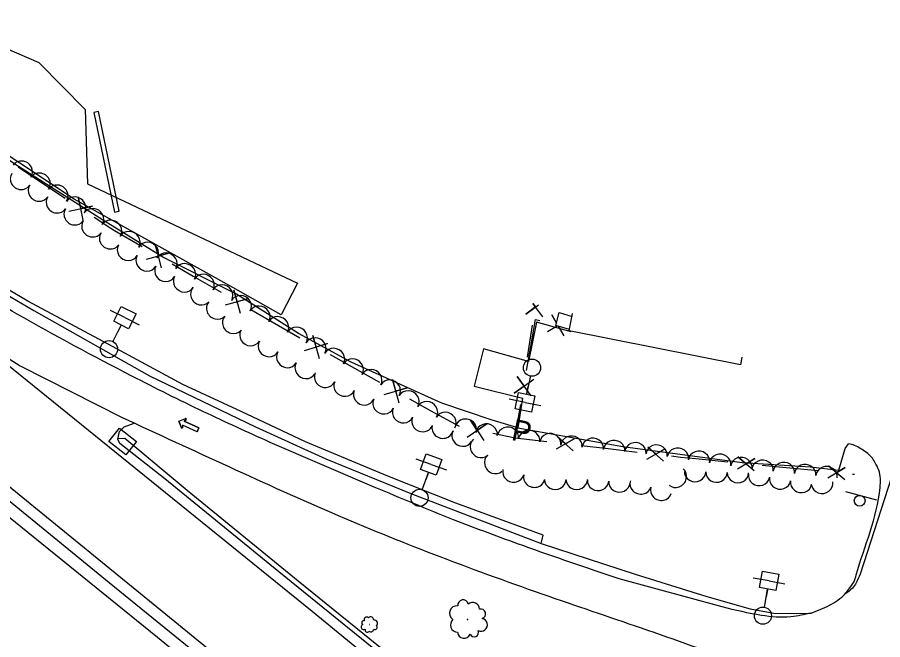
# Model space of a CAD drawing. Extents: x 1746010 to 1754829, y 655801 to 663091.
# Drawn here: x 1748666.3 to 1749070.2, y 661359.7 to 661650.3 of the extents above; entities that cross this region are included whole.
import ezdxf

# ---------------------------------------------------------------- set-up
doc = ezdxf.new("R2010")
doc.units = 0
for name, color, linetype in [('SURVEY - AERIAL SURVEY - Photo Control - Points - Elevations', 7, 'Continuous'), ('SURVEY - AERIAL SURVEY - Photo Control - Points - Locators', 7, 'Continuous'), ('SURVEY - AERIAL SURVEY - Photo Control - Points - Numbers', 7, 'Continuous'), ('SURVEY - AERIAL SURVEY - Photo Control with Text', 7, 'Continuous'), ('SURVEY - CENTERLINE - Existing Roads - Development', 7, 'Continuous'), ('SURVEY - CENTERLINE - Existing Roads Curve Text', 7, 'Continuous'), ('SURVEY - CENTERLINE - Existing Roads Text', 7, 'Continuous'), ('SURVEY - CENTERLINE - Preliminary - Development', 7, 'Continuous'), ('SURVEY - DRAINAGE - Area Shapes - Points - Elevations', 7, 'Continuous')]:
    doc.layers.add(name, color=color, linetype=linetype)

msp = doc.modelspace()

# ---------------------------------------------------------------- linework, layer by layer
at = {"layer": 'SURVEY - AERIAL SURVEY - Photo Control - Points - Elevations'}
for points in [[(1748910.83, 661404.62), (1748911.82, 661408.5), (1748870.98, 661423.43), (1748839.2, 661435.99), (1748800.89, 661452.08), (1748770.77, 661466.26), (1748743.52, 661478.84), (1748708.78, 661497.63), (1748671.19, 661517.75), (1748645.7, 661532.7), (1748625.37, 661545.71), (1748613.39, 661554.16), (1748594.67, 661567.82), (1748564.2, 661592.32), (1748517.09, 661629.66), (1748455.21, 661679.34), (1748447.39, 661684.85), (1748446.67, 661685.36)], [(1748713.37, 661453.65), (1748716.55, 661453.81), (1748746.53, 661428.67), (1748797.36, 661387.23), (1748840.72, 661352.13), (1748888.64, 661312.91), (1748914.18, 661293.34), (1748937.25, 661278.19), (1748959.67, 661261.1), (1748965.83, 661253.19), (1748993.44, 661229.06), (1749007.32, 661220.73), (1749023.86, 661206.7), (1749027.85, 661203.6), (1749026.76, 661197.6)]]:
    msp.add_lwpolyline(points, dxfattribs=at)
at = {"layer": 'SURVEY - AERIAL SURVEY - Photo Control - Points - Locators'}
for points in [[(1749014.37, 661130.26), (1748990.7, 661149.54), (1748916.31, 661209.97), (1748835.38, 661275.76), (1748731.71, 661360.72), (1748655.6, 661422.38), (1748555.07, 661504.4), (1748459.33, 661582.61), (1748380.29, 661646.59), (1748288.83, 661717.68), (1748181.12, 661800.02), (1748091.36, 661866.45), (1748036.84, 661905.72)], [(1748899.97, 661458.62), (1748887.43, 661462.28), (1748864.43, 661470.09), (1748846.92, 661477.99), (1748822.16, 661489.19), (1748797.58, 661502.72), (1748768.69, 661520.99), (1748734.27, 661538.32), (1748706.56, 661555.34), (1748665.21, 661581.73), (1748634.89, 661602.18), (1748596.11, 661629.48), (1748559.57, 661653.3), (1748537.78, 661666.72), (1748549.66, 661708.07), (1748583.03, 661703.96)], [(1748446.67, 661685.36), (1748447.41, 661681.83), (1748532.04, 661614.13), (1748593, 661565.86), (1748611.4, 661551.33), (1748626.29, 661541.43), (1748674.09, 661513.32), (1748727.97, 661482.88), (1748777.52, 661459.1), (1748810.35, 661444.15), (1748850.05, 661428.01), (1748910.83, 661404.62), (1748954.66, 661390.35), (1748988.16, 661379.8), (1749008.42, 661374.05)], [(1748523.79, 661544.26), (1748587.7, 661492.34), (1748672.29, 661423.24), (1748765.2, 661347.55), (1748850.45, 661278.14), (1748948.94, 661197.9), (1749016.8, 661142.7)], [(1748925.03, 661503.68), (1748924.84, 661503.41), (1748908.58, 661507.98), (1748904.89, 661489.51), (1748883.87, 661495.5), (1748879.53, 661478.04), (1748902.09, 661472.51), (1748899.97, 661458.62), (1748948.9, 661449.95), (1749004.58, 661442.45), (1749036.55, 661440.38), (1749049.7, 661438.78), (1749052.68, 661449.01), (1749054.28, 661451.18)], [(1749026.26, 661191.27), (1748981.31, 661227.83), (1748904.63, 661290.22), (1748803.87, 661372.8), (1748715.15, 661444.7), (1748642.21, 661503.71), (1748667.72, 661487.53), (1748715.24, 661463.43)], [(1749085.73, 661470.71), (1749059.7, 661390.3)], [(1749027.39, 661197.07), (1749014.65, 661207.7), (1748958.39, 661253.89), (1748897.1, 661302.67), (1748838.46, 661350.81), (1748788.42, 661391.33), (1748735.2, 661434.76), (1748714.24, 661451.33), (1748713.32, 661453.39), (1748714.02, 661456.96), (1748716.26, 661459.11), (1748720.91, 661460.82)], [(1748832.92, 661430.93), (1748784.36, 661451.78)], [(1748995.35, 661374.97), (1748947.23, 661388.08)], [(1749008.42, 661374.05), (1749019.46, 661372.08), (1749026.98, 661371.91), (1749036.87, 661372.11), (1749043.28, 661374.64)]]:
    msp.add_lwpolyline(points, dxfattribs=at)
for points in [[(1748784.36, 661451.78), (1748753.18, 661466.15), (1748719.83, 661482.77), (1748666.33, 661511.73), (1748631.65, 661532.7), (1748602.01, 661552.91), (1748569.65, 661577.83)], [(1748715.24, 661463.43), (1748765.05, 661440.48), (1748816.14, 661417.66), (1748863.57, 661398.48), (1748914.39, 661379.98), (1748960.41, 661364.19), (1749007.79, 661347.35)], [(1749043.28, 661374.64), (1749051.1, 661379.58), (1749053.01, 661381.51), (1749054.88, 661383.91), (1749056.72, 661386.54), (1749057.9, 661389.94), (1749069, 661430.77), (1749068.42, 661438.86), (1749066.55, 661442.56), (1749064.99, 661444.93), (1749062.61, 661447.05), (1749059.99, 661448.87), (1749057.13, 661450.35), (1749054.28, 661451.18)], [(1748947.23, 661388.08), (1748902.24, 661403.6), (1748869.95, 661415.71), (1748832.92, 661430.93)], [(1749059.7, 661390.3), (1749057.86, 661386.23), (1749056.09, 661383.72), (1749052.51, 661380.91)], [(1749036.87, 661372.11), (1749027.4, 661370.36), (1749013.73, 661371.02), (1748995.35, 661374.97)]]:
    msp.add_spline(points, degree=3, dxfattribs=at)
at = {"layer": 'SURVEY - AERIAL SURVEY - Photo Control - Points - Numbers'}
msp.add_lwpolyline([(1748040.01, 661910.33), (1748122.02, 661850.78), (1748195.38, 661796.53), (1748267.56, 661741.32), (1748333.52, 661690.82), (1748402.34, 661636.08), (1748451.04, 661597.23), (1748504.04, 661553.85), (1748559.78, 661508.8), (1748636.39, 661445.77), (1748709.27, 661386.44), (1748757.29, 661347.34), (1748822.35, 661294.7), (1748882.58, 661246), (1748955.33, 661186.03), (1749015.15, 661137.9)], dxfattribs=at)
at = {"layer": 'SURVEY - AERIAL SURVEY - Photo Control with Text'}
msp.add_line((1749052.88, 661428.94), (1749067.33, 661424.93), dxfattribs=at)
msp.add_lwpolyline([(1748713.87, 661559.76), (1748704.2, 661606.32), (1748702.03, 661605.86), (1748711.69, 661559.31)], close=True, dxfattribs=at)
msp.add_circle((1749059.49, 661424.56), 2.5, dxfattribs=at)
at = {"layer": 'SURVEY - CENTERLINE - Existing Roads - Development'}
for points in [[(1748570.53, 661675.05), (1748676.35, 661629.18), (1748697.97, 661607.26), (1748699.02, 661572.5), (1748797.11, 661526.2), (1748789.51, 661511.31), (1748766.93, 661524.11), (1748692.93, 661565.4), (1748629.58, 661607.2), (1748573.74, 661645.81), (1748539.15, 661666.94), (1748551.06, 661706.64), (1748584.59, 661702.79)], [(1748666.71, 661580.41), (1748676.22, 661574.12)], [(1748676.22, 661574.12), (1748688.72, 661565.85)], [(1748690.38, 661559.84), (1748701.38, 661562.16), (1748695.92, 661560.97), (1748694.79, 661566.52), (1748696.97, 661555.49)], [(1748702.15, 661556.98), (1748709.94, 661551.83), (1748711.72, 661550.79)], [(1748711.72, 661550.79), (1748724.68, 661543.24)], [(1748726.68, 661537.34), (1748737.53, 661540.28), (1748732.15, 661538.78), (1748730.71, 661544.25), (1748733.51, 661533.36)], [(1748738.59, 661535.15), (1748746.5, 661530.54), (1748748.45, 661529.42)], [(1748748.45, 661529.42), (1748761.44, 661521.92)], [(1748763.46, 661516.02), (1748774.3, 661518.99), (1748768.92, 661517.48), (1748767.46, 661522.94), (1748770.3, 661512.07)], [(1748907, 661516.7), (1748908.24, 661515.06), (1748903.68, 661511.72), (1748909.64, 661516.03)], [(1748911.58, 661510.49), (1748906.97, 661516.71)], [(1748775.38, 661513.86), (1748785.25, 661508.16)], [(1748924.02, 661504.54), (1748917.7, 661506.4), (1748919.18, 661512.4), (1748925.23, 661510.64)], [(1748785.25, 661508.16), (1748798.24, 661500.66)], [(1748905.95, 661496.64), (1748908.12, 661509.26), (1748910.25, 661508.7)], [(1748917.98, 661507.53), (1748915.77, 661511.29), (1748917.97, 661507.49)], [(1749004.52, 661491.61), (1749003.8, 661488), (1748923.89, 661503.91), (1748925.49, 661511.95)], [(1748904.52, 661491.66), (1748906.81, 661506.48)], [(1748913.76, 661503.55), (1748918.27, 661506.24)], [(1748918.79, 661506.08), (1748921.4, 661501.56)], [(1748800.34, 661494.76), (1748811.13, 661497.91), (1748805.78, 661496.31), (1748804.23, 661501.75), (1748807.24, 661490.92)], [(1748904.02, 661485.41), (1748905.95, 661496.64)], [(1748812.29, 661492.8), (1748822.26, 661487.27)], [(1748822.26, 661487.27), (1748835.36, 661479.97)], [(1748837.48, 661474.11), (1748848.27, 661477.26), (1748842.92, 661475.66), (1748841.37, 661481.1), (1748844.38, 661470.27)], [(1748906.13, 661473.48), (1748899.59, 661482.62), (1748902.87, 661478.1), (1748898.25, 661474.83), (1748907.47, 661481.26)], [(1748849.44, 661472.15), (1748859.4, 661466.61)], [(1748898.76, 661454.76), (1748901.3, 661469.54)], [(1748859.4, 661466.61), (1748872.51, 661459.32)], [(1748876.27, 661454.31), (1748885.61, 661460.57), (1748880.99, 661457.43), (1748877.87, 661462.14), (1748884.01, 661452.73)], [(1748888.26, 661456.06), (1748898.62, 661453.95), (1748898.76, 661454.76)], [(1748898.62, 661453.95), (1748913.51, 661452.22)], [(1748917.95, 661448.8), (1748926.23, 661453.5), (1748922.14, 661451.15), (1748918.39, 661454.41), (1748925.79, 661447.89)], [(1748929.49, 661450.36), (1748940.81, 661449.05)], [(1748940.81, 661449.05), (1748955.7, 661447.32)], [(1748960.14, 661443.9), (1748968.41, 661448.6), (1748964.33, 661446.24), (1748960.57, 661449.51), (1748967.98, 661442.98)], [(1748971.68, 661445.46), (1748975.92, 661444.96), (1748983, 661444.26)], [(1748983, 661444.26), (1748997.91, 661442.79)], [(1749002.45, 661439.44), (1749010.54, 661444.3), (1749006.55, 661441.86), (1749002.69, 661445.07), (1749010.3, 661438.66)], [(1749013.9, 661441.2), (1749025.23, 661440.08)], [(1749025.23, 661440.08), (1749040.14, 661438.61)], [(1749044.68, 661435.26), (1749052.77, 661440.12), (1749048.78, 661437.68), (1749044.92, 661440.89), (1749052.53, 661434.48)], [(1749056.13, 661437.03), (1749057.07, 661436.93)]]:
    msp.add_lwpolyline(points, dxfattribs=at)
at = {"layer": 'SURVEY - CENTERLINE - Existing Roads Curve Text'}
for p, q in [((1748716.56, 661510.08), (1748709.87, 661513.46)), ((1748716.56, 661510.08), (1748723.26, 661506.7)), ((1748710.89, 661498.83), (1748714.81, 661506.6)), ((1748714.63, 661506.24), (1748713.19, 661503.38)), ((1748905.79, 661482.85), (1748904.06, 661474.32)), ((1748904.14, 661474.71), (1748904.78, 661477.85)), ((1748903.29, 661470.5), (1748895.94, 661471.99)), ((1748903.29, 661470.5), (1748910.64, 661469.01)), ((1748859.5, 661441.47), (1748852.43, 661443.96)), ((1748859.5, 661441.47), (1748866.58, 661438.99)), ((1748855.33, 661429.59), (1748858.21, 661437.8)), ((1748858.08, 661437.42), (1748857.02, 661434.4)), ((1749017.21, 661387.14), (1749009.83, 661388.45)), ((1749017.21, 661387.14), (1749024.6, 661385.83)), ((1749015.01, 661374.73), (1749016.53, 661383.3)), ((1749016.46, 661382.91), (1749015.9, 661379.76))]:
    msp.add_line(p, q, dxfattribs=at)
for points in [[(1748721.8, 661511.8), (1748718.29, 661504.84), (1748711.32, 661508.35), (1748714.84, 661515.32)], [(1748898.69, 661467.45), (1748900.24, 661475.1), (1748907.89, 661473.55), (1748906.33, 661465.9)], [(1748864.48, 661443.86), (1748861.89, 661436.5), (1748854.53, 661439.09), (1748857.11, 661446.45)], [(1749021.74, 661390.3), (1749020.37, 661382.62), (1749012.69, 661383.98), (1749014.06, 661391.66)]]:
    msp.add_lwpolyline(points, close=True, dxfattribs=at)
for centre in [(1748709.13, 661495.35), (1748906.57, 661486.67), (1748854.03, 661425.91), (1749014.33, 661370.89)]:
    msp.add_circle(centre, 4, dxfattribs=at)
at = {"layer": 'SURVEY - CENTERLINE - Existing Roads Text'}
for centre, radius in [((1748830.66, 661366.8), 0.044), ((1748876.44, 661369.11), 0.105)]:
    msp.add_circle(centre, radius, dxfattribs=at)
for centre, radius, start, end in [((1748871.43, 661372.06), 3.4, 82.4383, 238.2768), ((1748874.36, 661375.77), 2.51, 12.6912, 187.6915), ((1748878.86, 661373.82), 3.23, 2.5323, 129.378), ((1748882.66, 661371.75), 2.28, 287.2452, 104.5644), ((1748828.07, 661365.65), 1.26, 109.852, 303.2717), ((1748827.96, 661367.65), 0.866, 69.8313, 248.5769), ((1748829.4, 661368.98), 1.26, 47.7151, 204.504), ((1748831.25, 661368.89), 1.44, 356.7679, 134.2921), ((1748833.02, 661367.42), 1.43, 307.6637, 103.5022), ((1748871.91, 661366.61), 3.42, 131.5425, 269.0667), ((1748882.71, 661366.64), 3, 244.6266, 78.0463), ((1748829.61, 661364.16), 0.958, 152.4706, 329.7898), ((1748831.35, 661364.68), 1.36, 227.7577, 354.6034), ((1748833.26, 661365.45), 1.05, 237.9166, 52.9169), ((1748874.85, 661363.32), 3, 182.4897, 339.2787), ((1748879.54, 661363.12), 2.06, 204.6059, 23.3515)]:
    msp.add_arc(centre, radius, start, end, dxfattribs=at)
for centre, major_axis in [((1748668.53, 661578.39), (4.14, -2.8)), ((1748667.95, 661574.63), (-4.19, 2.73)), ((1748676.82, 661572.79), (4.14, -2.8)), ((1748685.11, 661567.19), (4.14, -2.8)), ((1748676.33, 661569.17), (-4.19, 2.73)), ((1748684.69, 661563.69), (-4.14, 2.8)), ((1748693.42, 661561.63), (4.2, -2.71)), ((1748692.98, 661558.09), (-4.14, 2.8)), ((1748701.81, 661556.21), (4.2, -2.71)), ((1748701.27, 661552.5), (-4.14, 2.8)), ((1748710.2, 661550.79), (4.2, -2.71)), ((1748709.55, 661546.91), (-4.14, 2.8)), ((1748718.69, 661545.53), (4.33, -2.5)), ((1748727.35, 661540.52), (4.33, -2.5)), ((1748717.93, 661541.46), (-4.36, 2.45)), ((1748736.01, 661535.52), (4.33, -2.5)), ((1748726.65, 661536.56), (-4.36, 2.45)), ((1748735.37, 661531.67), (-4.36, 2.45)), ((1748744.67, 661530.52), (4.33, -2.5)), ((1748744.1, 661526.77), (-4.36, 2.45)), ((1748753.35, 661525.55), (4.34, -2.48)), ((1748752.05, 661520.81), (-3.72, 3.34)), ((1748762.04, 661520.6), (4.34, -2.48)), ((1748770.73, 661515.65), (4.34, -2.48)), ((1748759.49, 661514.13), (-3.72, 3.34)), ((1748779.41, 661510.7), (4.34, -2.48)), ((1748766.92, 661507.44), (-3.72, 3.34)), ((1748788.1, 661505.74), (4.34, -2.48)), ((1748775.04, 661501.68), (-4.3, 2.55)), ((1748796.8, 661500.82), (4.35, -2.46)), ((1748805.51, 661495.89), (4.35, -2.46)), ((1748783.64, 661496.57), (-4.3, 2.55)), ((1748814.21, 661490.97), (4.35, -2.46)), ((1748792.24, 661491.47), (-4.3, 2.55)), ((1748800.84, 661486.37), (-4.3, 2.55)), ((1748822.91, 661486.04), (4.35, -2.46)), ((1748809.9, 661482.17), (-4.56, 2.05)), ((1748831.61, 661481.11), (4.35, -2.46)), ((1748819.02, 661478.07), (-4.56, 2.05)), ((1748840.3, 661476.16), (4.33, -2.51)), ((1748828.13, 661473.98), (-4.56, 2.05)), ((1748848.95, 661471.15), (4.33, -2.51)), ((1748837.22, 661469.83), (-4.54, 2.09)), ((1748846.3, 661465.65), (-4.54, 2.09)), ((1748857.6, 661466.13), (4.33, -2.51)), ((1748855.38, 661461.48), (-4.54, 2.09)), ((1748866.26, 661461.12), (4.33, -2.51)), ((1748864.84, 661458.39), (-4.83, 1.28)), ((1748875.7, 661458), (4.82, -1.32)), ((1748885.42, 661455.75), (4.94, -0.75)), ((1748874.04, 661454.74), (-4.32, 2.51)), ((1748895.31, 661454.25), (4.94, -0.75)), ((1748905.19, 661452.74), (4.94, -0.75)), ((1748915.08, 661451.24), (4.94, -0.75)), ((1748882.53, 661449.53), (-3.33, 3.73)), ((1748925, 661450.11), (4.97, -0.52)), ((1748934.94, 661449.08), (4.97, -0.52)), ((1748944.88, 661448.05), (4.97, -0.52)), ((1748954.81, 661447.01), (4.97, -0.52)), ((1748964.74, 661445.91), (4.95, -0.72)), ((1748974.63, 661444.47), (4.95, -0.72)), ((1748984.52, 661443.02), (4.95, -0.72)), ((1748889.18, 661442.08), (-3.33, 3.73)), ((1748994.41, 661441.58), (4.95, -0.72)), ((1749004.29, 661440.14), (4.95, -0.72)), ((1749014.19, 661438.81), (4.98, -0.5)), ((1748973.87, 661435.62), (-3.28, -3.77)), ((1749024.12, 661437.81), (4.98, -0.5)), ((1749034.05, 661436.81), (4.98, -0.5)), ((1749043.98, 661435.82), (4.98, -0.5)), ((1748897.84, 661437.93), (-4.85, 1.21)), ((1748907.54, 661435.51), (-4.85, 1.21)), ((1748982.66, 661438.12), (-5, 0.12)), ((1748992.65, 661437.88), (-5, 0.12)), ((1749002.65, 661437.64), (-5, 0.12)), ((1749012.5, 661436.31), (-4.93, 0.82)), ((1749022.32, 661434.68), (-4.93, 0.82)), ((1748917.42, 661434.5), (-5, 0.01)), ((1748927.41, 661434.48), (-5, 0.01)), ((1748937.37, 661434), (-4.99, 0.35)), ((1748947.33, 661433.3), (-4.99, 0.35)), ((1748957.25, 661432.37), (-4.78, 1.48)), ((1749032.13, 661433.05), (-4.93, 0.82)), ((1749041.97, 661432.65), (-4.93, -0.81)), ((1748966.8, 661429.41), (-4.78, 1.48))]:
    msp.add_ellipse(centre, major_axis=major_axis, ratio=0.940188, start_param=0, end_param=3.141593, dxfattribs=at)
at = {"layer": 'SURVEY - CENTERLINE - Preliminary - Development'}
msp.add_line((1748715.5, 661452.22), (1748715.5, 661452.22), dxfattribs=at)
msp.add_lwpolyline([(1748709.1, 661452.22), (1748714.09, 661458.47), (1748721.9, 661452.22), (1748716.91, 661445.97), (1748709.1, 661452.22)], dxfattribs=at)
at = {"layer": 'SURVEY - DRAINAGE - Area Shapes - Points - Elevations'}
for p, q in [((1748741.73, 661461.77), (1748744.89, 661462.95)), ((1748741.73, 661461.77), (1748744.89, 661462.95)), ((1748742.91, 661458.6), (1748741.73, 661461.77)), ((1748741.73, 661461.77), (1748742.91, 661458.6)), ((1748743.43, 661459.91), (1748743.38, 661458.68)), ((1748743.43, 661459.91), (1748743.38, 661458.68)), ((1748750.27, 661456.78), (1748743.43, 661459.91)), ((1748750.27, 661456.78), (1748743.43, 661459.91)), ((1748745.15, 661462.54), (1748744.25, 661461.7)), ((1748744.25, 661461.7), (1748745.15, 661462.54)), ((1748744.25, 661461.7), (1748751.08, 661458.57)), ((1748751.08, 661458.57), (1748744.25, 661461.7)), ((1748751.08, 661458.57), (1748750.27, 661456.78)), ((1748750.27, 661456.78), (1748751.08, 661458.57))]:
    msp.add_line(p, q, dxfattribs=at)
for centre, start, end in [((1748744.98, 661462.72), 312.9491, 110.3974), ((1748744.98, 661462.72), 312.9491, 110.3974), ((1748743.14, 661458.69), 200.3974, 357.8905), ((1748743.14, 661458.69), 200.3974, 357.8905)]:
    msp.add_arc(centre, 0.246, start, end, dxfattribs=at)

# ---------------------------------------------------------------- texts
at = {"layer": 'SURVEY - CENTERLINE - Existing Roads Curve Text'}
msp.add_text('P', height=10, rotation=348.5239, dxfattribs=at).set_placement((1748896.47, 661453.01))

doc.saveas('drawing.dxf')
